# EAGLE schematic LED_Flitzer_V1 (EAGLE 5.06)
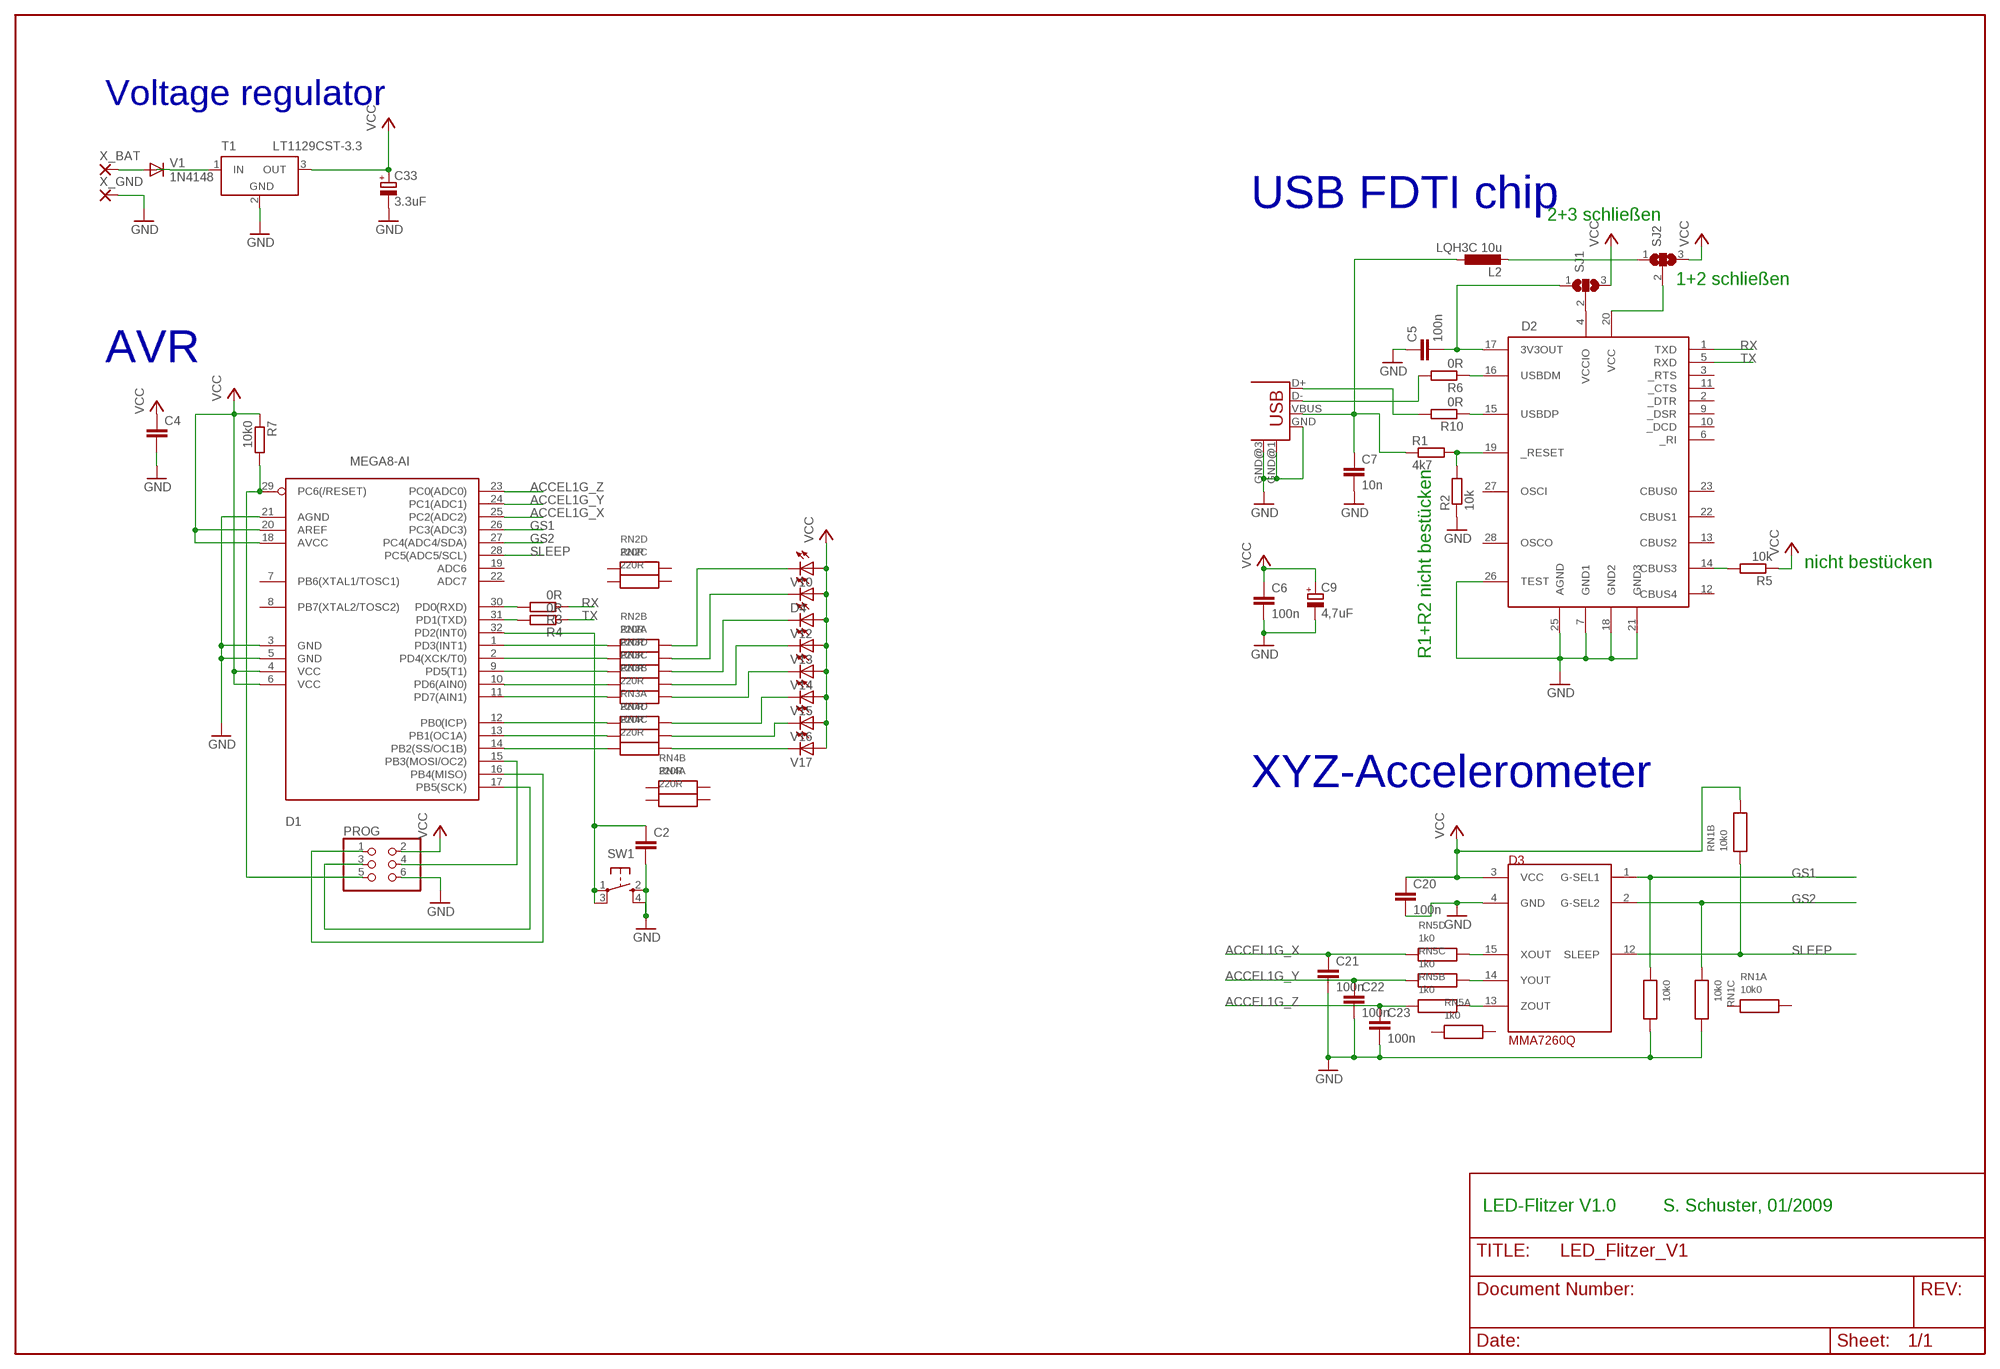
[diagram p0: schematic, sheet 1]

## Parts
C2  C-EUC0805  [C0805]
C4  C-EUC0805  [C0805]
C5  100n  C-EUC1206  [C1206]
C6  100n  C-EUC1206  [C1206]
C7  10n  C-EUC1206  [C1206]
C9  4,7uF  CPOL-EUCT6032  [CT6032]
C20  100n  C-EUC1206  [C1206]
C21  100n  C-EUC1206  [C1206]
C22  100n  C-EUC1206  [C1206]
C23  100n  C-EUC1206  [C1206]
C33  3.3uF  CPOL-EUCT6032  [CT6032]
D1  MEGA8-AI  [TQFP32-08]
D2  FT232RL  [SSOP28DB]
D3  MMA7260Q  [QFN16]
D4  LEDCHIPLED_1206  [CHIPLED_1206]
L2  LQH3C 10u  L-EUL3225P  [L3225P]
PROG  PINHD-2X3  [2X03]
R1  4k7  R-EU_M1206  [M1206]
R2  10k  R-EU_M1206  [M1206]
R3  0R  R-EU_M1206  [M1206]
R4  0R  R-EU_M1206  [M1206]
R5  10k  R-EU_M1206  [M1206]
R6  0R  R-EU_M1206  [M1206]
R7  10k0  R-EU_M1206  [M1206]
R10  0R  R-EU_M1206  [M1206]
RN1  10k0  4X1-12061206  [1206]
RN2  220R  4X1-12061206  [1206]
RN3  220R  4X1-12061206  [1206]
RN4  220R  4X1-12061206  [1206]
RN5  1k0  4X1-12061206  [1206]
SJ1  SJ2W  [SJ_2]
SJ2  SJ2W  [SJ_2]
SW1  CK_TACTSWITCHJ-LEAD  [CK_KT11_JM]
T1  LT1129CST-3.3  LT1129CST5  [SOT223]
USB1  USB BWM SMD  USB-MB-S  [USB-MB-S]
V1  1N4148  [DO35-10]
V10  LEDCHIPLED_1206  [CHIPLED_1206]
V12  LEDCHIPLED_1206  [CHIPLED_1206]
V13  LEDCHIPLED_1206  [CHIPLED_1206]
V14  LEDCHIPLED_1206  [CHIPLED_1206]
V15  LEDCHIPLED_1206  [CHIPLED_1206]
V16  LEDCHIPLED_1206  [CHIPLED_1206]
V17  LEDCHIPLED_1206  [CHIPLED_1206]
X_BAT  2,15/1,0  [2,15/1,0]
X_GND  2,15/1,0  [2,15/1,0]

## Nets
ACCEL1G_X: C21.1 D1.25(PC2(ADC2)) RN5.R4A(D:A)
ACCEL1G_Y: C22.1 D1.24(PC1(ADC1)) RN5.R3A(C:A)
ACCEL1G_Z: C23.1 D1.23(PC0(ADC0)) RN5.R2A(B:A)
GND [power]: C2.2 C4.2 C5.1 C6.2 C7.2 C9.- C20.2 C21.2 C22.2 C23.2 C33.- D1.3(GND) D1.5(GND) D1.21(AGND) D2.7(GND1) D2.18(GND2) D2.21(GND3) D2.25(AGND) D2.26(TEST) D3.4(GND) PROG.6 R2.1 RN1.R3B(C:B) RN1.R4B(D:B) SW1.2(S) SW1.4(S1) T1.2(GND) USB1.GND USB1.GND@1(GND) USB1.GND@3(GND) X_GND.1(P)
GS1: D1.26(PC3(ADC3)) D3.1(G-SEL1) RN1.R4A(D:A)
GS2: D1.27(PC4(ADC4/SDA)) D3.2(G-SEL2) RN1.R3A(C:A)
N$3: R6.2 USB1.D-
N$4: R10.2 USB1.D+
N$5: D1.30(PD0(RXD)) R3.2
N$6: D1.31(PD1(TXD)) R4.2
N$7: D1.1(PD3(INT1)) RN2.R2A(B:A)
N$8: D1.2(PD4(XCK/T0)) RN2.R1A(A:A)
N$9: D1.9(PD5(T1)) RN3.R4A(D:A)
N$10: D1.10(PD6(AIN0)) RN3.R3A(C:A)
N$11: D1.11(PD7(AIN1)) RN3.R2A(B:A)
N$12: D1.12(PB0(ICP)) RN3.R1A(A:A)
N$14: D2.20(VCC) SJ2.2
N$15: D1.15(PB3(MOSI/OC2)) PROG.4
N$16: D1.17(PB5(SCK)) PROG.3
N$17: C2.1 D1.32(PD2(INT0)) SW1.1(P) SW1.3(P1)
N$18: D1.29(PC6(/RESET)) PROG.5 R7.2
N$19: D1.16(PB4(MISO)) PROG.1
N$20: D1.13(PB1(OC1A)) RN4.R4A(D:A)
N$21: D1.14(PB2(SS/OC1B)) RN4.R3A(C:A)
N$24: D2.19(_RESET) R1.2 R2.2
N$27: RN2.R2B(B:B) V10.C
N$29: RN3.R4B(D:B) V12.C
N$30: RN3.R3B(C:B) V13.C
N$31: RN3.R2B(B:B) V14.C
N$32: RN3.R1B(A:B) V15.C
N$33: RN4.R4B(D:B) V16.C
N$34: RN4.R3B(C:B) V17.C
N$35: C7.1 L2.1 R1.1 USB1.VBUS
N$39: C5.2 D2.17(3V3OUT) SJ1.1
N$40: D2.14(CBUS3) R5.2
N$41: D2.16(USBDM) R6.1
N$42: D2.15(USBDP) R10.1
N$43 [power]: V1.A X_BAT.1(P)
N$44: L2.2 SJ2.1
N$45: D2.4(VCCIO) SJ1.2
N$46 [power]: T1.1(IN) V1.C
N$72: D3.15(XOUT) RN5.R4B(D:B)
N$73: D3.14(YOUT) RN5.R3B(C:B)
N$74: D3.13(ZOUT) RN5.R2B(B:B)
RX: D2.1(TXD) R3.1
SLEEP: D1.28(PC5(ADC5/SCL)) D3.12(SLEEP) RN1.R2A(B:A)
TX: D2.5(RXD) R4.1
V11: D4.C RN2.R1B(A:B)
VCC [power]: C4.1 C6.1 C9.+ C20.1 C33.+ D1.4(VCC) D1.6(VCC) D1.18(AVCC) D1.20(AREF) D3.3(VCC) D4.A PROG.2 R5.1 R7.1 RN1.R2B(B:B) SJ1.3 SJ2.3 T1.3(OUT) V10.A V12.A V13.A V14.A V15.A V16.A V17.A
Unconnected: D1.7(PB6(XTAL1/TOSC1)) D1.8(PB7(XTAL2/TOSC2)) D1.19(ADC6) D1.22(ADC7) D2.2(_DTR) D2.3(_RTS) D2.6(_RI) D2.9(_DSR) D2.10(_DCD) D2.11(_CTS) D2.12(CBUS4) D2.13(CBUS2) D2.22(CBUS1) D2.23(CBUS0) D2.27(OSCI) D2.28(OSCO) RN1.R1A(A:A) RN1.R1B(A:B) RN2.R3A(C:A) RN2.R3B(C:B) RN2.R4A(D:A) RN2.R4B(D:B) RN4.R1A(A:A) RN4.R1B(A:B) RN4.R2A(B:A) RN4.R2B(B:B) RN5.R1A(A:A) RN5.R1B(A:B)

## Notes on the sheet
- Voltage regulator
- USB FDTI chip
- 2+3 schließen
- 1+2 schließen
- AVR
- nicht bestücken
- R1+R2 nicht bestücken
- XYZ-Accelerometer
- LED-Flitzer V1.0 | S. Schuster, 01/2009

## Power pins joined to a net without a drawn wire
GND: T1.4(GND)

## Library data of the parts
C2 C4 = proj:C-EU: CAPACITOR, European symbol
C5-C7 C20-C23 = rcl:C-EU: CAPACITOR, European symbol
C9 C33 = rcl:CPOL-EU: POLARIZED CAPACITOR, European symbol
D1 = proj:MEGA8: MICROCONTROLLER 8 Kbytes FLASH 1 kbytes SRAM 512 bytes EEPROM USART 6-channel 10 bit ADC 2-channel 8 bit ADC
D2 = ftdichip:FT232RL: USB UART 4th Generation USB UART (USB <-> Serial) Controller
D3 = my_freescale_mma:MMA7260Q
D4 V10 V12-V17 = proj:LED: LED
L2 = rcl:L-EU: INDUCTOR, European symbol
PROG = proj:PINHD-2X3: PIN HEADER
R1-R7 R10 = rcl:R-EU_: RESISTOR, European symbol
RN1-RN5 = arrays:4X1-1206
SJ1 SJ2 = jumper:SJ2W: SMD solder JUMPER
SW1 = proj:CK_TACTSWITCH: C&K tactile switches
T1 = linear-technology:LT1129CST5: VOLTAGE REGULATOR with shutdown
USB1 = con-usb-2:USB: USB Connectors
V1 = diode:1N4148: DIODE
X_BAT X_GND = wirepad:2,15/1,0: THROUGH-HOLE PAD

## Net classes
1 power: width 0.305 mm, drill 0.61 mm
